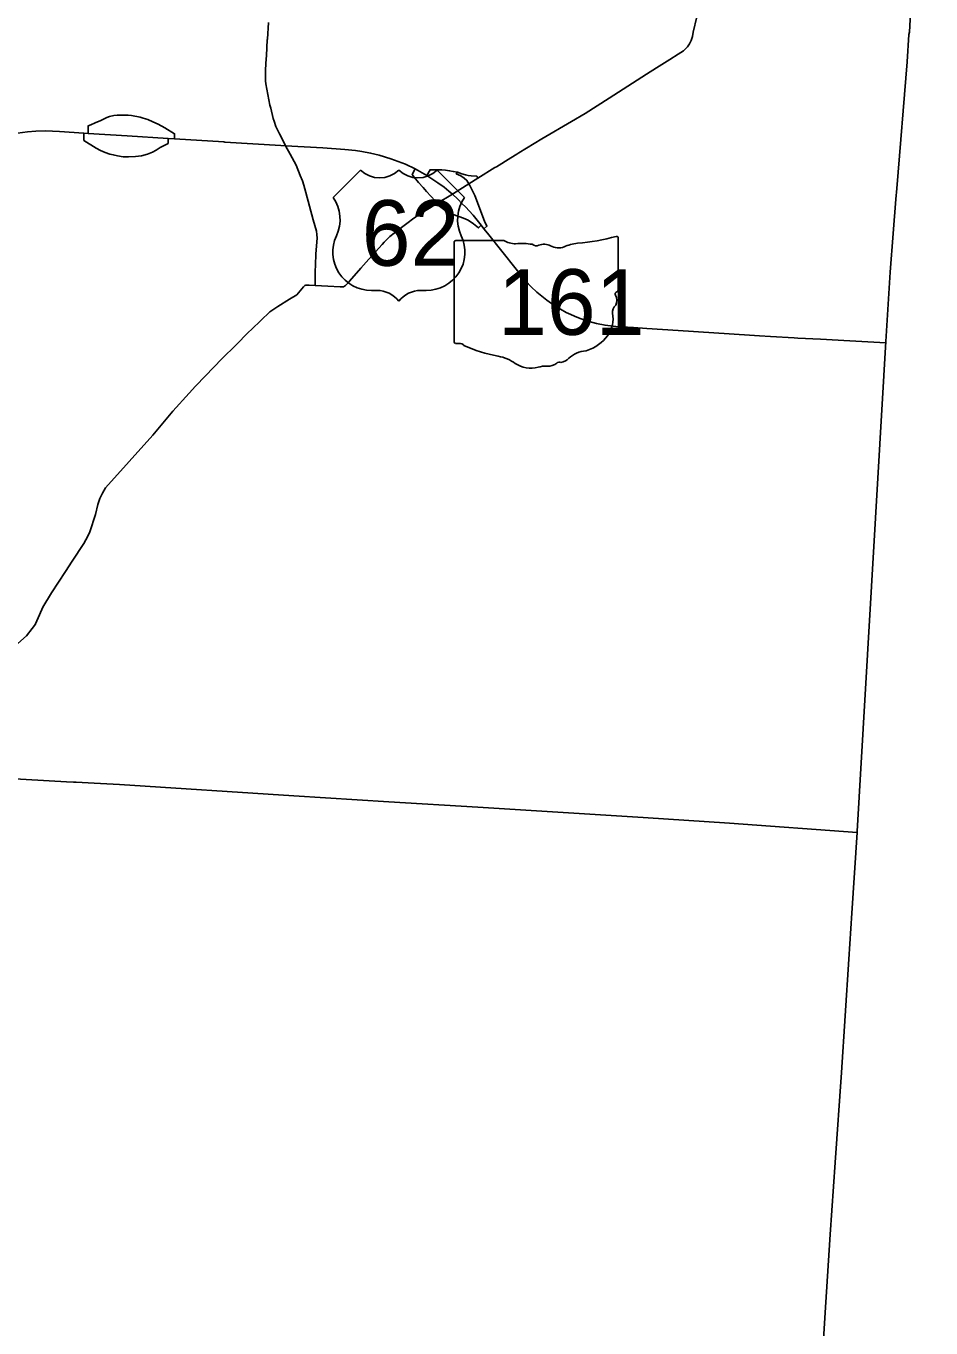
# Model space of a CAD drawing. Extents: x -1146 to -445, y -1283 to -822.
# Drawn here: x -765.1 to -717.2, y -1003.9 to -934.9 of the extents above; entities that cross this region are included whole.
import ezdxf

# ---------------------------------------------------------------- set-up
doc = ezdxf.new("R2010")
doc.units = 0
for name, color, linetype in [('GM_X_County', 7, 'Continuous'), ('GM_X_Interchange_Ramps', 7, 'Continuous'), ('GM_X_State_Route', 7, 'Continuous'), ('GM_X_State_Shield', 7, 'Continuous'), ('GM_X_Township', 7, 'Continuous'), ('GM_X_US_Route', 7, 'Continuous'), ('GM_X_US_Shield', 7, 'Continuous')]:
    doc.layers.add(name, color=color, linetype=linetype)

msp = doc.modelspace()

# ---------------------------------------------------------------- linework, layer by layer
at = {"layer": 'GM_X_County'}
msp.add_lwpolyline([(-717.154, -914.053), (-718.295, -935.196), (-718.327, -935.317), (-718.412, -936.771), (-718.965, -943.497), (-719.01, -944.048), (-719.157, -945.873), (-719.324, -947.931), (-719.553, -951.612), (-721.068, -977.583), (-721.067, -977.642), (-721.356, -981.918), (-721.516, -984.361), (-721.891, -990.381), (-722.229, -995.144), (-722.5, -998.966), (-722.786, -1003.387), (-723.025, -1007.4)], dxfattribs=at)
at = {"layer": 'GM_X_Interchange_Ramps'}
for points in [[(-759.71, -939.609), (-759.891, -939.599), (-760.297, -939.607), (-760.486, -939.621), (-760.709, -939.677), (-760.848, -939.726), (-761.167, -939.876), (-761.467, -940.009), (-761.689, -940.118), (-761.843, -940.173), (-761.846, -940.568)], [(-757.27, -940.85), (-757.258, -940.585), (-757.776, -940.265), (-758.121, -940.087), (-758.416, -939.946), (-758.677, -939.836), (-758.917, -939.752), (-759.076, -939.709), (-759.536, -939.626), (-759.71, -939.609)], [(-762.063, -940.554), (-762.074, -940.937), (-761.409, -941.35), (-761.177, -941.475), (-760.939, -941.584), (-760.691, -941.662), (-760.511, -941.703), (-760.278, -941.761), (-759.975, -941.808), (-759.846, -941.811)], [(-759.846, -941.811), (-759.695, -941.806), (-759.335, -941.799), (-759.018, -941.766), (-758.697, -941.669), (-758.427, -941.557), (-758.234, -941.452), (-758.028, -941.324), (-757.81, -941.203), (-757.601, -941.096), (-757.589, -940.83)], [(-744.507, -942.449), (-744.656, -942.756), (-744.551, -942.894), (-744.322, -943.175), (-744.084, -943.446), (-743.894, -943.649), (-743.439, -944.145), (-743.353, -944.285)], [(-741.172, -942.943), (-741.238, -942.839), (-741.527, -942.822), (-741.687, -942.8), (-741.831, -942.763), (-742.019, -942.711), (-742.264, -942.631), (-742.483, -942.582), (-742.679, -942.548), (-742.885, -942.524), (-743.082, -942.508), (-743.707, -942.496), (-743.875, -942.802)], [(-741.649, -943.239), (-741.761, -943.063), (-741.912, -942.939), (-742.079, -942.821), (-742.323, -942.707), (-742.264, -942.631)], [(-740.86, -945.627), (-740.694, -945.491), (-740.818, -945.22), (-741.346, -943.866), (-741.436, -943.643), (-741.599, -943.328), (-741.649, -943.239)], [(-743.353, -944.285), (-743.278, -944.383), (-743.143, -944.482), (-742.928, -944.637), (-742.716, -944.759), (-742.487, -944.864), (-741.944, -945.064), (-741.695, -945.177), (-741.415, -945.356), (-741.149, -945.579), (-741.01, -945.44)]]:
    msp.add_lwpolyline(points, dxfattribs=at)
at = {"layer": 'GM_X_State_Route'}
for points in [[(-752.338, -935.567), (-752.277, -934.68)], [(-752.413, -936.836), (-752.388, -936.441), (-752.34, -935.599), (-752.338, -935.567)], [(-751.368, -941.222), (-751.543, -940.9), (-751.701, -940.591), (-751.882, -940.197), (-751.977, -939.926), (-752.023, -939.782), (-752.158, -939.238), (-752.201, -939.075), (-752.412, -937.937), (-752.429, -937.778), (-752.444, -937.556), (-752.438, -937.245), (-752.413, -936.836)], [(-769.971, -942.178), (-769.057, -941.746), (-768.141, -941.323), (-767.751, -941.156), (-767.285, -940.986), (-766.901, -940.865), (-766.374, -940.723), (-766.031, -940.64), (-765.578, -940.557), (-765.064, -940.489), (-764.619, -940.45), (-764.103, -940.437), (-763.354, -940.47), (-762.063, -940.554), (-761.846, -940.568), (-759.773, -940.701), (-757.589, -940.83), (-757.27, -940.85), (-754.647, -941.023)], [(-754.647, -941.023), (-754.6, -941.026), (-751.631, -941.206)], [(-751.631, -941.206), (-751.368, -941.222), (-749.401, -941.339), (-748.223, -941.419), (-747.657, -941.477), (-747.338, -941.523), (-746.868, -941.614), (-746.411, -941.728), (-745.791, -941.915), (-745.007, -942.205), (-744.507, -942.449), (-743.875, -942.802), (-743.295, -943.187), (-742.97, -943.428), (-742.724, -943.631)], [(-750.297, -943.699), (-750.399, -943.309), (-750.479, -943.086), (-750.593, -942.8), (-750.815, -942.248), (-751.121, -941.674), (-751.368, -941.222)], [(-749.723, -945.926), (-749.738, -945.752), (-749.914, -945.157), (-750.297, -943.699)], [(-742.724, -943.631), (-742.525, -943.796), (-742.231, -944.064), (-742.004, -944.301), (-741.84, -944.455), (-741.426, -944.912), (-741.01, -945.44), (-740.86, -945.627), (-740.67, -945.858), (-739.146, -947.766), (-738.637, -948.403), (-738.344, -948.714), (-738.058, -948.981), (-737.521, -949.416), (-737.103, -949.712), (-736.493, -950.069)], [(-749.789, -947.549), (-749.76, -946.963), (-749.705, -946.126), (-749.723, -945.926)], [(-749.809, -948.632), (-749.804, -947.867), (-749.789, -947.549)], [(-736.493, -950.069), (-736.373, -950.122)], [(-736.373, -950.122), (-735.925, -950.318), (-735.468, -950.488), (-734.889, -950.653), (-734.434, -950.739), (-733.865, -950.802), (-732.933, -950.869)], [(-732.933, -950.869), (-732.223, -950.919), (-730.55, -951.022), (-726.769, -951.265)], [(-726.769, -951.265), (-726.245, -951.299)], [(-726.245, -951.299), (-725.66, -951.336), (-724.408, -951.409)], [(-724.408, -951.409), (-724.208, -951.421), (-723.003, -951.487), (-721.457, -951.576), (-719.553, -951.677)]]:
    msp.add_lwpolyline(points, dxfattribs=at)
at = {"layer": 'GM_X_State_Shield'}
for p, q in [((-742.434, -946.342), (-742.434, -951.625)), ((-739.801, -946.251), (-742.349, -946.251)), ((-733.733, -948.883), (-733.733, -946.12)), ((-733.734, -948.883), (-733.733, -948.883))]:
    msp.add_line(p, q, dxfattribs=at)
for centre, major_axis, start_param, end_param in [((-742.335, -946.33), (0.101, 0), 1.712693, 3.28349), ((-739.194, -945.637), (0.978, 0), 4.042523, 4.731795), ((-738.87, -949.217), (3.51, 0), 1.404758, 1.657858), ((-738.073, -946.303), (0.282, 0), 3.836095, 5.185415), ((-737.659, -946.914), (0.586, 0), 0.950623, 2.079405), ((-736.902, -946.076), (0.705, 0), 4.081561, 5.145723), ((-735.656, -947.864), (1.856, 0), 1.699011, 2.107814), ((-736.833, -939.048), (9.227, 0), 4.814394, 5.042369), ((-733.83, -946.108), (0.0969, 0), 6.141152, 7.989035), ((-733.756, -949.086), (0.15, 0), 1.883978, 3.671073), ((-734.71, -949.436), (0.9, 0), 5.934695, 6.695948), ((-733.837, -948.894), (0.104, 0), 5.05454, 6.418171), ((-736.316, -950.392), (2.308, 0), 5.101752, 6.440018), ((-733.386, -950.04), (0.655, 0), 2.387724, 3.262537), ((-742.334, -951.636), (0.102, 0), 3.00124, 4.508301), ((-742.318, -951.096), (0.776, 0), 4.665946, 4.897461), ((-742.16, -951.93), (0.28, 0), 0.519207, 1.627899), ((-738.627, -947.183), (6.663, 0), 4.195997, 4.488961), ((-735.343, -953.108), (1.264, 0), 1.647645, 2.488434), ((-740.613, -953.998), (2.085, 0), 0.823519, 1.323587), ((-738.358, -951.956), (1.323, 0), 4.026481, 4.996735), ((-737.497, -952.351), (0.705, 0), 4.691044, 5.507374), ((-736.86, -952.863), (0.198, 0), 1.147584, 2.315152), ((-736.944, -952.137), (0.746, 0), 4.937069, 5.64225), ((-737.594, -953.782), (1.087, 0), 1.495662, 1.94098)]:
    msp.add_ellipse(centre, major_axis=major_axis, ratio=0.8, start_param=start_param, end_param=end_param, dxfattribs=at)
at = {"layer": 'GM_X_Township'}
msp.add_lwpolyline([(-768.805, -974.625), (-762.996, -974.951), (-762.61, -974.971), (-762.476, -974.981), (-761.526, -975.03), (-760.178, -975.098), (-750.938, -975.695), (-745.902, -976.014), (-741.176, -976.304), (-732.405, -976.857), (-727.83, -977.158), (-721.067, -977.642)], dxfattribs=at)
at = {"layer": 'GM_X_US_Route'}
for points in [[(-730.176, -936.09), (-730.065, -935.982), (-729.957, -935.824), (-729.864, -935.649), (-729.804, -935.426), (-729.754, -935.206), (-729.573, -934.388)], [(-731.697, -937.095), (-730.992, -936.65), (-730.558, -936.372), (-730.414, -936.279), (-730.273, -936.185), (-730.176, -936.09)], [(-736.208, -939.931), (-735.494, -939.513), (-734.217, -938.701), (-732.235, -937.435), (-731.697, -937.095)], [(-738.997, -941.599), (-737.789, -940.856), (-736.208, -939.931)], [(-739.435, -941.867), (-739.108, -941.667), (-738.997, -941.599)], [(-742.131, -943.546), (-741.649, -943.239), (-741.172, -942.943), (-740.269, -942.379), (-740.197, -942.335)], [(-740.197, -942.335), (-739.435, -941.867)], [(-744.868, -945.29), (-744.641, -945.109), (-744.241, -944.837), (-743.749, -944.532), (-743.353, -944.285), (-742.525, -943.796), (-742.131, -943.546)], [(-746.257, -946.459), (-746.15, -946.342), (-745.841, -946.042), (-745.149, -945.514), (-744.868, -945.29)], [(-747.381, -947.72), (-746.966, -947.239), (-746.257, -946.459)], [(-747.975, -948.409), (-747.381, -947.72)], [(-750.767, -949.127), (-750.415, -948.706), (-750.378, -948.666), (-750.345, -948.64), (-750.292, -948.613), (-750.127, -948.612), (-749.809, -948.632), (-749.127, -948.665), (-748.481, -948.705), (-748.308, -948.7), (-748.191, -948.634), (-748.031, -948.474), (-747.975, -948.409)], [(-753.164, -950.953), (-752.204, -950.032), (-752.044, -949.923), (-751.783, -949.747), (-751.164, -949.363), (-750.767, -949.127)], [(-764.629, -966.573), (-764.417, -966.105), (-764.244, -965.691), (-763.791, -964.937), (-763.039, -963.798), (-762.69, -963.263), (-762.066, -962.316), (-761.858, -961.933), (-761.745, -961.698), (-761.459, -960.786), (-761.321, -960.241), (-761.22, -959.932), (-761.139, -959.757), (-761.082, -959.65), (-760.914, -959.374), (-758.419, -956.577), (-757.346, -955.297), (-756.49, -954.339), (-756.147, -953.981), (-755.611, -953.427), (-754.745, -952.533), (-753.998, -951.788), (-753.354, -951.135), (-753.164, -950.953)], [(-769.995, -971.616), (-769.805, -971.439), (-768.68, -970.417), (-766.961, -968.871), (-765.412, -967.488), (-765.108, -967.208), (-764.802, -966.833), (-764.638, -966.594), (-764.629, -966.573)]]:
    msp.add_lwpolyline(points, dxfattribs=at)
at = {"layer": 'GM_X_US_Shield'}
for p, q in [((-747.397, -942.512), (-748.847, -943.962)), ((-741.887, -943.962), (-743.337, -942.512)), ((-746.817, -948.893), (-746.527, -948.893)), ((-744.207, -948.893), (-743.917, -948.893))]:
    msp.add_line(p, q, dxfattribs=at)
for centre, radius, start, end in [((-746.382, -941.476), 1.45, 225.573, 314.427), ((-744.352, -941.476), 1.45, 225.573, 314.427), ((-750.511, -945.127), 2.03, 334.54712, 35.00093), ((-740.223, -945.127), 2.03, 144.99907, 205.45288), ((-746.84, -946.863), 2.03, 154.83192, 270.63826), ((-743.894, -946.863), 2.03, 269.36174, 25.16808), ((-746.527, -950.343), 1.45, 36.8699, 90), ((-744.207, -950.343), 1.45, 90, 143.1301)]:
    msp.add_arc(centre, radius, start, end, dxfattribs=at)

# ---------------------------------------------------------------- texts
at = {"layer": 'GM_X_State_Shield'}
msp.add_text('161', height=3.4805, dxfattribs=at).set_placement((-740.108, -951.252))
at = {"layer": 'GM_X_US_Shield'}
msp.add_text('62', height=3.4805, dxfattribs=at).set_placement((-747.337, -947.588))

doc.saveas('drawing.dxf')
